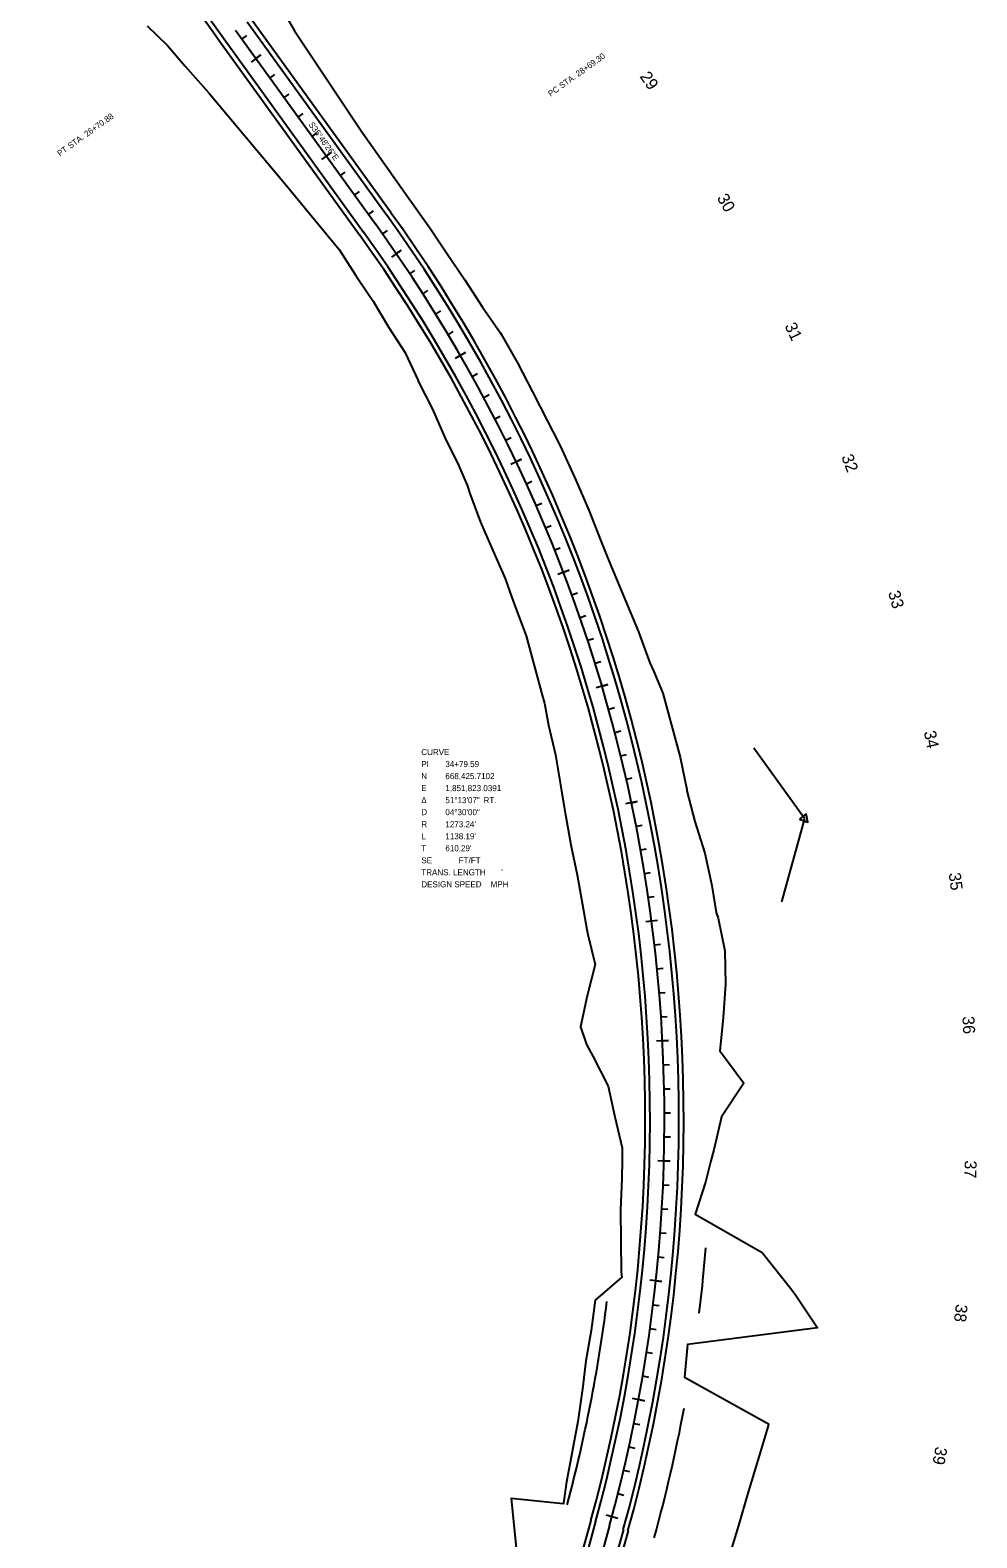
# Model space of a CAD drawing. Extents: x 1849567 to 1851966, y 666813 to 670457.
# Drawn here: x 1851179 to 1851966, y 667827 to 669082 of the extents above; entities that cross this region are included whole.
import ezdxf

# ---------------------------------------------------------------- set-up
doc = ezdxf.new("R2010")
doc.units = 0
for name, color, linetype in [('_CIVIL_CONSTRUCTION', 7, 'Continuous'), ('Default', 7, 'Continuous'), ('DES - CL - Proposed', 7, 'Continuous'), ('DES - CL - Proposed Curve Text', 7, 'Continuous'), ('DES - CL - Proposed Text', 7, 'Continuous'), ('DES - CL - Proposed Text - Large', 7, 'Continuous'), ('DES - CL - Proposed Text - Small', 7, 'Continuous'), ('DES - MODEL - Lines - Cut Slopes', 7, 'Continuous'), ('DES - MODEL - Lines - Ditch Centerline', 7, 'Continuous'), ('DES - MODEL - Lines - Pavement Edge', 7, 'Continuous'), ('DES - MODEL - Lines - Shoulder Edge', 7, 'Continuous')]:
    doc.layers.add(name, color=color, linetype=linetype)

msp = doc.modelspace()

# ---------------------------------------------------------------- linework, layer by layer
at = {"layer": '_CIVIL_CONSTRUCTION'}
for p, q in [((1851349.9, 669081.6), (1851466, 668920.6)), ((1851660.9, 667837.4), (1851399.9, 666890.8))]:
    msp.add_line(p, q, dxfattribs=at)
msp.add_arc((1850433.4, 668175.7), 1273.2, 344.5884, 35.8071, dxfattribs=at)
at = {"layer": 'Default'}
for p, q in [((1851349.9, 669081.6), (1851466, 668920.6)), ((1851349.9, 669081.6), (1851466, 668920.6)), ((1851660.9, 667837.4), (1851399.9, 666890.8)), ((1851660.9, 667837.4), (1851399.9, 666890.8))]:
    msp.add_line(p, q, dxfattribs=at)
msp.add_arc((1850433.4, 668175.7), 1273.2, 344.5884, 35.8071, dxfattribs=at)
msp.add_arc((1850433.4, 668175.7), 1273.2, 344.5884, 35.8071, dxfattribs=at)
at = {"layer": 'DES - CL - Proposed'}
for p, q in [((1851349.9, 669081.6), (1851466, 668920.6)), ((1851660.9, 667837.4), (1851399.9, 666890.8))]:
    msp.add_line(p, q, dxfattribs=at)
msp.add_arc((1850433.4, 668175.7), 1273.2, 344.5884, 35.8071, dxfattribs=at)
at = {"layer": 'DES - CL - Proposed Text'}
for q in [(1851780.9, 668484.1), (1851780.9, 668484.1), (1851803.9, 668356.3), (1851803.9, 668356.3), (1851823, 668425.7), (1851823, 668425.7)]:
    msp.add_line((1851823, 668425.7), q, dxfattribs=at)
msp.add_lwpolyline([(1851818.9, 668425), (1851825.7, 668422.5), (1851824.4, 668429.6)], close=True, dxfattribs=at)
msp.add_lwpolyline([(1851818.9, 668425), (1851825.7, 668422.5), (1851824.4, 668429.6)], close=True, dxfattribs=at)
at = {"layer": 'DES - CL - Proposed Text - Large'}
for p, q in [((1851366.9, 669057.9), (1851371, 669060.9)), ((1851366.9, 669057.9), (1851371, 669060.9)), ((1851425.4, 668976.8), (1851429.5, 668979.8)), ((1851425.4, 668976.8), (1851429.5, 668979.8)), ((1851483.6, 668895.5), (1851487.8, 668898.4)), ((1851483.6, 668895.5), (1851487.8, 668898.4)), ((1851541.2, 668813.4), (1851532.5, 668808.4)), ((1851541.2, 668813.4), (1851532.5, 668808.4)), ((1851583.3, 668722.4), (1851587.8, 668724.5)), ((1851583.3, 668722.4), (1851587.8, 668724.5)), ((1851622.7, 668630.5), (1851627.3, 668632.2)), ((1851622.7, 668630.5), (1851627.3, 668632.2)), ((1851654.7, 668535.8), (1851659.5, 668537.2)), ((1851654.7, 668535.8), (1851659.5, 668537.2)), ((1851679.2, 668438.8), (1851684, 668439.9)), ((1851679.2, 668438.8), (1851684, 668439.9)), ((1851700.9, 668340.9), (1851691, 668339.6)), ((1851700.9, 668340.9), (1851691, 668339.6)), ((1851705, 668240.7), (1851710, 668241)), ((1851705, 668240.7), (1851710, 668241)), ((1851706.2, 668140.7), (1851711.1, 668140.6)), ((1851706.2, 668140.7), (1851711.1, 668140.6)), ((1851699.5, 668041), (1851704.4, 668040.5)), ((1851699.5, 668041), (1851704.4, 668040.5)), ((1851685, 667942.1), (1851689.9, 667941.2)), ((1851685, 667942.1), (1851689.9, 667941.2)), ((1851667.7, 667843.3), (1851658, 667845.9)), ((1851667.7, 667843.3), (1851658, 667845.9))]:
    msp.add_line(p, q, dxfattribs=at)
at = {"layer": 'DES - CL - Proposed Text - Small'}
for p, q in [((1851355.2, 669074.2), (1851359.3, 669077.1)), ((1851355.2, 669074.2), (1851359.3, 669077.1)), ((1851371, 669060.9), (1851362.9, 669055)), ((1851371, 669060.9), (1851362.9, 669055)), ((1851378.6, 669041.7), (1851382.7, 669044.6)), ((1851378.6, 669041.7), (1851382.7, 669044.6)), ((1851390.3, 669025.5), (1851394.4, 669028.4)), ((1851390.3, 669025.5), (1851394.4, 669028.4)), ((1851402, 669009.3), (1851406.1, 669012.2)), ((1851402, 669009.3), (1851406.1, 669012.2)), ((1851413.7, 668993.1), (1851417.8, 668996)), ((1851413.7, 668993.1), (1851417.8, 668996)), ((1851429.5, 668979.8), (1851421.4, 668973.9)), ((1851429.5, 668979.8), (1851421.4, 668973.9)), ((1851437.1, 668960.6), (1851441.2, 668963.5)), ((1851437.1, 668960.6), (1851441.2, 668963.5)), ((1851448.8, 668944.4), (1851452.9, 668947.3)), ((1851448.8, 668944.4), (1851452.9, 668947.3)), ((1851460.5, 668928.2), (1851464.6, 668931.1)), ((1851460.5, 668928.2), (1851464.6, 668931.1)), ((1851472.2, 668911.9), (1851476.3, 668914.8)), ((1851472.2, 668911.9), (1851476.3, 668914.8)), ((1851487.8, 668898.4), (1851479.5, 668892.7)), ((1851487.8, 668898.4), (1851479.5, 668892.7)), ((1851494.8, 668878.9), (1851499, 668881.7)), ((1851494.8, 668878.9), (1851499, 668881.7)), ((1851505.7, 668862.2), (1851509.9, 668864.9)), ((1851505.7, 668862.2), (1851509.9, 668864.9)), ((1851516.4, 668845.3), (1851520.6, 668847.9)), ((1851516.4, 668845.3), (1851520.6, 668847.9)), ((1851526.8, 668828.2), (1851531, 668830.7)), ((1851526.8, 668828.2), (1851531, 668830.7)), ((1851541.2, 668813.4), (1851532.5, 668808.4)), ((1851541.2, 668813.4), (1851532.5, 668808.4)), ((1851546.7, 668793.5), (1851551.1, 668795.9)), ((1851546.7, 668793.5), (1851551.1, 668795.9)), ((1851556.3, 668775.9), (1851560.7, 668778.3)), ((1851556.3, 668775.9), (1851560.7, 668778.3)), ((1851565.6, 668758.2), (1851570, 668760.5)), ((1851565.6, 668758.2), (1851570, 668760.5)), ((1851574.6, 668740.4), (1851579.1, 668742.6)), ((1851574.6, 668740.4), (1851579.1, 668742.6)), ((1851587.8, 668724.5), (1851578.8, 668720.2)), ((1851587.8, 668724.5), (1851578.8, 668720.2)), ((1851591.8, 668704.2), (1851596.3, 668706.3)), ((1851591.8, 668704.2), (1851596.3, 668706.3)), ((1851599.9, 668686), (1851604.5, 668688)), ((1851599.9, 668686), (1851604.5, 668688)), ((1851607.8, 668667.6), (1851612.4, 668669.5)), ((1851607.8, 668667.6), (1851612.4, 668669.5)), ((1851615.4, 668649.1), (1851620, 668650.9)), ((1851615.4, 668649.1), (1851620, 668650.9)), ((1851627.3, 668632.3), (1851618, 668628.7)), ((1851627.3, 668632.3), (1851618, 668628.7)), ((1851629.7, 668611.7), (1851634.3, 668613.4)), ((1851629.7, 668611.7), (1851634.3, 668613.4)), ((1851636.4, 668592.9), (1851641.1, 668594.5)), ((1851636.4, 668592.9), (1851641.1, 668594.5)), ((1851642.8, 668573.9), (1851647.5, 668575.5)), ((1851642.8, 668573.9), (1851647.5, 668575.5)), ((1851648.9, 668554.9), (1851653.6, 668556.4)), ((1851648.9, 668554.9), (1851653.6, 668556.4)), ((1851659.5, 668537.2), (1851649.9, 668534.3)), ((1851659.5, 668537.2), (1851649.9, 668534.3)), ((1851660.2, 668516.5), (1851665, 668517.9)), ((1851660.2, 668516.5), (1851665, 668517.9)), ((1851665.4, 668497.2), (1851670.2, 668498.5)), ((1851665.4, 668497.2), (1851670.2, 668498.5)), ((1851670.3, 668477.8), (1851675.1, 668479)), ((1851670.3, 668477.8), (1851675.1, 668479)), ((1851674.9, 668458.4), (1851679.7, 668459.5)), ((1851674.9, 668458.4), (1851679.7, 668459.5)), ((1851684, 668439.9), (1851674.3, 668437.8)), ((1851684, 668439.9), (1851674.3, 668437.8)), ((1851683.1, 668419.2), (1851688, 668420.2)), ((1851683.1, 668419.2), (1851688, 668420.2)), ((1851686.8, 668399.6), (1851691.7, 668400.4)), ((1851686.8, 668399.6), (1851691.7, 668400.4)), ((1851690.2, 668379.9), (1851695.1, 668380.7)), ((1851690.2, 668379.9), (1851695.1, 668380.7)), ((1851693.2, 668360.1), (1851698.1, 668360.8)), ((1851693.2, 668360.1), (1851698.1, 668360.8)), ((1851700.9, 668340.9), (1851691, 668339.6)), ((1851700.9, 668340.9), (1851691, 668339.6)), ((1851698.4, 668320.4), (1851703.3, 668321)), ((1851698.4, 668320.4), (1851703.3, 668321)), ((1851700.5, 668300.5), (1851705.5, 668301)), ((1851700.5, 668300.5), (1851705.5, 668301)), ((1851702.3, 668280.6), (1851707.3, 668281)), ((1851702.3, 668280.6), (1851707.3, 668281)), ((1851703.8, 668260.7), (1851708.8, 668261)), ((1851703.8, 668260.7), (1851708.8, 668261)), ((1851710, 668241), (1851700, 668240.5)), ((1851710, 668241), (1851700, 668240.5)), ((1851705.8, 668220.7), (1851710.8, 668220.9)), ((1851705.8, 668220.7), (1851710.8, 668220.9)), ((1851706.4, 668200.7), (1851711.4, 668200.8)), ((1851706.4, 668200.7), (1851711.4, 668200.8)), ((1851706.6, 668180.7), (1851711.6, 668180.8)), ((1851706.6, 668180.7), (1851711.6, 668180.8)), ((1851706.5, 668160.7), (1851711.5, 668160.7)), ((1851706.5, 668160.7), (1851711.5, 668160.7)), ((1851711.2, 668140.6), (1851701.2, 668140.9)), ((1851711.2, 668140.6), (1851701.2, 668140.9)), ((1851705.5, 668120.8), (1851710.4, 668120.5)), ((1851705.5, 668120.8), (1851710.4, 668120.5)), ((1851704.4, 668100.8), (1851709.4, 668100.5)), ((1851704.4, 668100.8), (1851709.4, 668100.5)), ((1851703.1, 668080.8), (1851708.1, 668080.5)), ((1851703.1, 668080.8), (1851708.1, 668080.5)), ((1851701.4, 668060.9), (1851706.4, 668060.4)), ((1851701.4, 668060.9), (1851706.4, 668060.4)), ((1851704.5, 668040.5), (1851694.5, 668041.5)), ((1851704.5, 668040.5), (1851694.5, 668041.5)), ((1851697.2, 668021.1), (1851702.2, 668020.5)), ((1851697.2, 668021.1), (1851702.2, 668020.5)), ((1851694.6, 668001.3), (1851699.6, 668000.6)), ((1851694.6, 668001.3), (1851699.6, 668000.6)), ((1851691.7, 667981.5), (1851696.7, 667980.7)), ((1851691.7, 667981.5), (1851696.7, 667980.7)), ((1851688.5, 667961.8), (1851693.4, 667960.9)), ((1851688.5, 667961.8), (1851693.4, 667960.9)), ((1851689.9, 667941.2), (1851680.1, 667943)), ((1851689.9, 667941.2), (1851680.1, 667943)), ((1851681.2, 667922.4), (1851686.1, 667921.5)), ((1851681.2, 667922.4), (1851686.1, 667921.5)), ((1851677.1, 667902.9), (1851681.9, 667901.8)), ((1851677.1, 667902.9), (1851681.9, 667901.8)), ((1851672.6, 667883.4), (1851677.5, 667882.2)), ((1851672.6, 667883.4), (1851677.5, 667882.2)), ((1851667.9, 667863.9), (1851672.7, 667862.7)), ((1851667.9, 667863.9), (1851672.7, 667862.7)), ((1851667.7, 667843.3), (1851658, 667845.9)), ((1851667.7, 667843.3), (1851658, 667845.9))]:
    msp.add_line(p, q, dxfattribs=at)
at = {"layer": 'DES - MODEL - Lines - Cut Slopes'}
for points in [[(1851384.3, 669106.4), (1851399, 669081.1), (1851454.5, 668997.8), (1851494.4, 668941.2), (1851510.1, 668918.9), (1851512.5, 668915.3), (1851525.4, 668896.4), (1851540.5, 668873.8), (1851555.2, 668851.1), (1851555.3, 668851), (1851570, 668830), (1851570.9, 668828.5), (1851584.5, 668804.9), (1851596.9, 668780.6), (1851609.3, 668756.3), (1851618.2, 668739), (1851621.6, 668732), (1851632.9, 668707.2), (1851643.8, 668682.2), (1851653.7, 668656.8), (1851658.7, 668644.3), (1851663.9, 668631.4), (1851674.4, 668606.2), (1851685, 668580.9), (1851694.5, 668555.2), (1851697.5, 668548.4), (1851705.3, 668529.9), (1851712.4, 668503.3), (1851719.7, 668476.8), (1851725.1, 668449.9), (1851725.3, 668448.6), (1851731.7, 668423.2), (1851740.1, 668396.8), (1851746, 668369.8), (1851749.7, 668347.3), (1851751.2, 668342.7), (1851756.9, 668315.5), (1851757.2, 668287.8), (1851755.5, 668260), (1851753.6, 668243.2), (1851752.5, 668232.3), (1851772.6, 668205.3), (1851754.1, 668177.4), (1851747.7, 668150.1), (1851744.9, 668139.7), (1851740.8, 668123), (1851732.1, 668096.3), (1851787.8, 668064.6), (1851812.6, 668033.6), (1851816.1, 668028.6), (1851833.8, 668001.9), (1851725.7, 667988), (1851723.3, 667960.9), (1851793.2, 667921.9), (1851792.7, 667920.2), (1851784.6, 667892.5), (1851776.3, 667865), (1851768.1, 667837.5), (1851762.3, 667818.3)], [(1851276.5, 669085.1), (1851293.4, 669068.9), (1851308.2, 669051.5), (1851327.6, 669029.6), (1851392, 668952.7), (1851436, 668899), (1851450, 668877.5), (1851452.3, 668874.1), (1851464.3, 668856.1), (1851477.5, 668834.1), (1851491.3, 668812.7), (1851491.4, 668812.5), (1851501.4, 668790.5), (1851502, 668789), (1851513.6, 668766.1), (1851524, 668742.7), (1851535.2, 668719.7), (1851542.5, 668703), (1851544.7, 668696), (1851553.7, 668672.1), (1851563.8, 668648.7), (1851574.2, 668625.4), (1851578.3, 668613.5), (1851582.6, 668601.3), (1851591.5, 668577.5), (1851598.2, 668552.9), (1851605, 668528.3), (1851606.8, 668521.6), (1851610.2, 668503.4), (1851616.1, 668478.7), (1851620.2, 668453.6), (1851624.3, 668428.5), (1851624.5, 668427.3), (1851628.7, 668403.6), (1851633.9, 668378.8), (1851638.5, 668353.9), (1851641.9, 668333.2), (1851642.9, 668329), (1851649, 668304.1), (1851642.4, 668278.1), (1851636.9, 668252.4), (1851641.7, 668237.5), (1851647, 668227.8), (1851659.7, 668202.8), (1851665.4, 668177.3), (1851671.5, 668151.6), (1851671.3, 668141.7), (1851671.2, 668125.8), (1851670, 668100.1), (1851670.4, 668074.2), (1851670.5, 668048.3), (1851671.1, 668044), (1851649, 668024.9), (1851645.6, 667999.7), (1851641.3, 667974.5), (1851638.4, 667950.8), (1851638.1, 667949.2), (1851634.6, 667924), (1851629.9, 667898.8), (1851625.1, 667873.7), (1851622.5, 667855.9), (1851622.4, 667855.5), (1851579.2, 667859.9), (1851589, 667761.2)]]:
    msp.add_lwpolyline(points, dxfattribs=at)
at = {"layer": 'DES - MODEL - Lines - Ditch Centerline'}
msp.add_lwpolyline([(1851740.8, 668068.4), (1851738.2, 668041.3), (1851737.8, 668036.9), (1851735.2, 668014.2)], dxfattribs=at)
for radius, start, end in [(1234.7, 344.9255, 352.9264), (1311.8, 344.5884, 349.4254)]:
    msp.add_arc((1850433.4, 668175.7), radius, start, end, dxfattribs=at)
at = {"layer": 'DES - MODEL - Lines - Pavement Edge'}
for p, q in [((1851359.6, 669088.6), (1851475.7, 668927.7)), ((1851340.2, 669074.5), (1851456.3, 668913.6)), ((1851649.3, 667840.6), (1851445.3, 667100.6)), ((1851672.4, 667834.2), (1851468.5, 667094.3))]:
    msp.add_line(p, q, dxfattribs=at)
for centre, radius, start, end in [((1852013.7, 669560.4), 830.5, 167.9203, 215.8072), ((1850433.4, 668175.7), 1285.2, 344.5884, 35.8071), ((1850433.4, 668175.7), 1261.2, 344.5884, 35.8071)]:
    msp.add_arc(centre, radius, start, end, dxfattribs=at)
at = {"layer": 'DES - MODEL - Lines - Shoulder Edge'}
for p, q in [((1851362.9, 669090.9), (1851479, 668930)), ((1851336.9, 669072.2), (1851453, 668911.3)), ((1851645.4, 667841.6), (1851441.5, 667101.7)), ((1851676.3, 667833.1), (1851472.3, 667093.2))]:
    msp.add_line(p, q, dxfattribs=at)
for centre, radius, start, end in [((1852013.7, 669560.4), 834.5, 167.9203, 215.8072), ((1850433.4, 668175.7), 1289.2, 344.5884, 35.8071), ((1850433.4, 668175.7), 1257.2, 344.5884, 35.8071)]:
    msp.add_arc(centre, radius, start, end, dxfattribs=at)

# ---------------------------------------------------------------- texts
at = {"layer": 'DES - CL - Proposed Curve Text'}
for s, p in [('28+69.30', (1851635.1, 669042.6)), ('28+69.30', (1851635.1, 669042.6)), (' STA. ', (1851619.8, 669031.6)), (' STA. ', (1851619.8, 669031.6)), ('PC', (1851612, 669026)), ('PC', (1851612, 669026)), ('26+70.88', (1851226.4, 668992.5)), ('26+70.88', (1851226.4, 668992.5)), (' STA. ', (1851211.1, 668981.5)), (' STA. ', (1851211.1, 668981.5)), ('PT', (1851203.9, 668976.3)), ('PT', (1851203.9, 668976.3))]:
    msp.add_text(s, height=4.98, rotation=35.8071, dxfattribs=at).set_placement(p)
for s, p in [('CURVE    ', (1851504.4, 668478.4)), ('CURVE    ', (1851504.4, 668478.4)), ('PI', (1851504.4, 668468.4)), ('PI', (1851504.4, 668468.4)), ('N', (1851504.4, 668458.4)), ('N', (1851504.4, 668458.4)), ('34+79.59', (1851524.4, 668468.4)), ('34+79.59', (1851524.4, 668468.4)), ('668,425.7102', (1851524.4, 668458.4)), ('668,425.7102', (1851524.4, 668458.4)), ('E', (1851504.4, 668448.4)), ('E', (1851504.4, 668448.4)), ('1,851,823.0391', (1851524.4, 668448.4)), ('1,851,823.0391', (1851524.4, 668448.4)), ('Δ', (1851504.4, 668438.4)), ('Δ', (1851504.4, 668438.4)), ('51°13\'07"', (1851524.4, 668438.4)), ('51°13\'07"', (1851524.4, 668438.4)), (' RT.', (1851554.3, 668438.4)), (' RT.', (1851554.3, 668438.4)), ('D', (1851504.4, 668428.4)), ('D', (1851504.4, 668428.4)), ('04°30\'00"', (1851524.4, 668428.4)), ('04°30\'00"', (1851524.4, 668428.4)), ('R', (1851504.4, 668418.4)), ('R', (1851504.4, 668418.4)), ('L', (1851504.4, 668408.4)), ('L', (1851504.4, 668408.4)), ("1273.24'", (1851524.4, 668418.4)), ("1273.24'", (1851524.4, 668418.4)), ("1138.19'", (1851524.4, 668408.4)), ("1138.19'", (1851524.4, 668408.4)), ('T', (1851504.4, 668398.4)), ('T', (1851504.4, 668398.4)), ("610.29'", (1851524.4, 668398.4)), ("610.29'", (1851524.4, 668398.4)), ('SE', (1851504.4, 668388.4)), ('SE', (1851504.4, 668388.4)), ('      FT/FT', (1851524.4, 668388.4)), ('      FT/FT', (1851524.4, 668388.4)), ("TRANS. LENGTH       '", (1851504.4, 668378.4)), ("TRANS. LENGTH       '", (1851504.4, 668378.4)), ('DESIGN SPEED    MPH', (1851504.4, 668368.4)), ('DESIGN SPEED    MPH', (1851504.4, 668368.4))]:
    msp.add_text(s, height=5, dxfattribs=at).set_placement(p)
at = {"layer": 'DES - CL - Proposed Text'}
msp.add_text('S35°48\'26"E', height=4.98, rotation=305.8071, dxfattribs=at).set_placement((1851410.4, 669002.9))
msp.add_text('S35°48\'26"E', height=4.98, rotation=305.8071, dxfattribs=at).set_placement((1851410.4, 669002.9))
at = {"layer": 'DES - CL - Proposed Text - Large'}
for s, rotation, p in [('30', 299.9254, (1851749.9, 668942)), ('30', 299.9254, (1851749.9, 668942)), ('35', 277.4254, (1851942.9, 668380)), ('35', 277.4254, (1851942.9, 668380))]:
    msp.add_text(s, height=9.96, rotation=rotation, dxfattribs=at).set_placement(p)
at = {"layer": 'DES - CL - Proposed Text - Small'}
for s, rotation, p in [('29', 304.4254, (1851685.7, 669043)), ('29', 304.4254, (1851685.7, 669043)), ('30', 299.9254, (1851749.9, 668942)), ('30', 299.9254, (1851749.9, 668942)), ('31', 295.4254, (1851806.3, 668835.5)), ('31', 295.4254, (1851806.3, 668835.5)), ('32', 290.9254, (1851853.5, 668726.6)), ('32', 290.9254, (1851853.5, 668726.6)), ('33', 286.4254, (1851892.4, 668613.6)), ('33', 286.4254, (1851892.4, 668613.6)), ('34', 281.9254, (1851922.2, 668497.7)), ('34', 281.9254, (1851922.2, 668497.7)), ('35', 277.4254, (1851942.9, 668380)), ('35', 277.4254, (1851942.9, 668380)), ('36', 272.9254, (1851954.3, 668260.9)), ('36', 272.9254, (1851954.3, 668260.9)), ('37', 268.4254, (1851956.3, 668141.3)), ('37', 268.4254, (1851956.3, 668141.3)), ('38', 263.9254, (1851948.9, 668021.9)), ('38', 263.9254, (1851948.9, 668021.9)), ('39', 259.4254, (1851932.1, 667903.5)), ('39', 259.4254, (1851932.1, 667903.5))]:
    msp.add_text(s, height=9.96, rotation=rotation, dxfattribs=at).set_placement(p)

doc.saveas('drawing.dxf')
